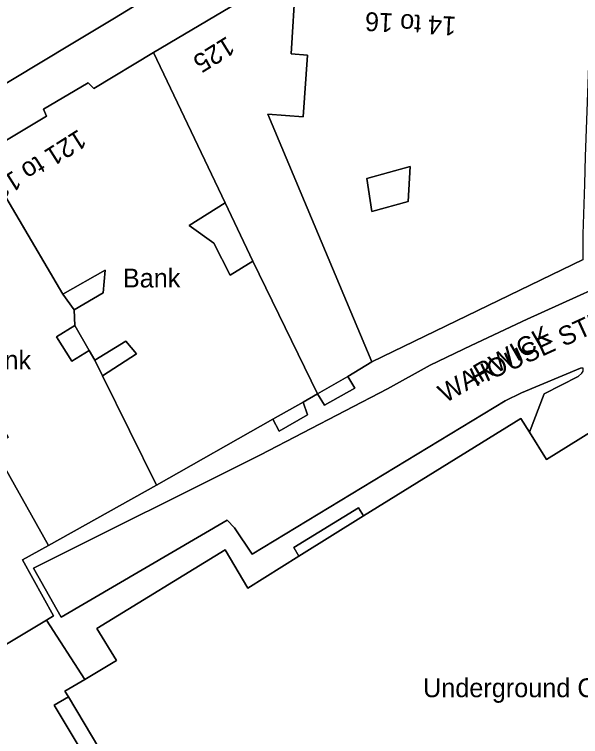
# Model space of a CAD drawing. Extents: x 529240 to 530363, y 179600 to 180767.
# Drawn here: x 529784.9 to 529829.9, y 180337.8 to 180395.2 of the extents above; entities that cross this region are included whole.
import ezdxf

# ---------------------------------------------------------------- set-up
doc = ezdxf.new("R2010")
doc.units = 0
for name, color, linetype in [('Building', 7, 'Continuous'), ('General surface', 7, 'Continuous'), ('Road Or Track', 7, 'Continuous'), ('Roadside', 7, 'Continuous'), ('Unclassified', 7, 'Continuous')]:
    doc.layers.add(name, color=color, linetype=linetype)

msp = doc.modelspace()

# ---------------------------------------------------------------- linework, layer by layer
at = {"layer": 'Building'}
for points in [[(529813.35, 180367.55), (529805.1, 180387.25), (529807.9, 180387.05), (529808.25, 180391.95), (529806.95, 180392.05), (529807.3, 180397.7), (529806.95, 180397.7), (529806.85, 180397.72), (529806.65, 180397.75), (529806.05, 180397.75), (529805.75, 180397.7), (529805.5, 180397.6), (529805.35, 180397.6), (529805.05, 180397.45), (529804.75, 180397.35), (529804.55, 180397.25), (529796, 180392.15), (529801.7, 180380.2), (529803.9, 180375.55), (529809.05, 180365), (529811.45, 180366.4)], [(529830.35, 180383.9), (529830.8, 180396.15), (529807.3, 180397.7), (529806.95, 180392.05), (529808.25, 180391.95), (529807.9, 180387.05), (529805.1, 180387.25), (529813.35, 180367.55), (529830.15, 180375.7), (529830.15, 180377.7), (529830.3, 180381.7)], [(529779.6, 180368.55), (529780.15, 180368.9), (529784.45, 180361.55), (529783.2, 180360.85), (529787.65, 180352.95), (529796.25, 180357.75), (529791.95, 180366.45), (529791.35, 180367.7), (529790.9, 180368.45), (529789.5, 180367.6), (529788.3, 180369.55), (529789.75, 180370.45), (529789.7, 180371.7), (529788.8, 180372.95), (529782.55, 180383.55), (529778.4, 180381), (529778.8, 180380.25), (529775.05, 180378.15), (529774.65, 180378.65), (529773.9, 180378.2), (529774.3, 180377.5)], [(529816.25, 180380.3), (529813.35, 180379.5), (529812.95, 180382.15), (529816.4, 180383.1)], [(529789.25, 180340.9), (529788.1, 180340.25), (529803.05, 180315.3), (529806.65, 180309.3), (529807.7, 180309.9)]]:
    msp.add_lwpolyline(points, close=True, dxfattribs=at)
for points in [[(529807.3, 180397.7), (529806.95, 180397.7), (529806.85, 180397.72), (529806.65, 180397.75), (529806.05, 180397.75), (529805.75, 180397.7), (529805.5, 180397.6), (529805.35, 180397.6), (529805.05, 180397.45), (529804.75, 180397.35), (529804.55, 180397.25), (529796, 180392.15)], [(529813.35, 180367.55), (529805.1, 180387.25), (529807.9, 180387.05), (529808.25, 180391.95), (529806.95, 180392.05), (529807.3, 180397.7)], [(529782.55, 180383.55), (529788.8, 180372.95), (529792.15, 180374.85), (529792, 180373.05), (529789.7, 180371.7), (529789.75, 180370.45), (529790.9, 180368.45), (529791.35, 180367.7), (529793.8, 180369.2), (529794.65, 180368.2), (529791.95, 180366.45), (529796.25, 180357.75), (529805.5, 180363), (529807.9, 180364.35), (529809.05, 180365), (529803.9, 180375.55), (529802.1, 180374.45), (529800.8, 180377), (529798.85, 180378.4), (529801.7, 180380.2), (529796, 180392.15), (529791.25, 180389.3), (529790.8, 180389.75), (529787.25, 180387.65), (529787.5, 180387.1), (529782.3, 180384)], [(529796, 180392.15), (529791.25, 180389.3), (529790.8, 180389.75), (529787.25, 180387.65), (529787.5, 180387.1), (529782.3, 180384), (529782.55, 180383.55)], [(529796, 180392.15), (529801.7, 180380.2)], [(529782.55, 180383.55), (529788.8, 180372.95)], [(529816.25, 180380.3), (529816.4, 180383.1), (529812.95, 180382.15), (529813.35, 180379.5), (529816.25, 180380.3)], [(529801.7, 180380.2), (529798.85, 180378.4), (529800.8, 180377), (529802.1, 180374.45), (529803.9, 180375.55)], [(529801.7, 180380.2), (529803.9, 180375.55)], [(529830.15, 180375.7), (529813.35, 180367.55)], [(529803.9, 180375.55), (529809.05, 180365)], [(529788.8, 180372.95), (529792.15, 180374.85), (529792, 180373.05), (529789.7, 180371.7)], [(529788.8, 180372.95), (529789.7, 180371.7)], [(529789.7, 180371.7), (529789.75, 180370.45)], [(529790.9, 180368.45), (529789.5, 180367.6), (529788.3, 180369.55), (529789.75, 180370.45)], [(529789.75, 180370.45), (529790.9, 180368.45)], [(529842.65, 180369.35), (529827.25, 180359.8), (529825.9, 180361.95), (529825.2, 180363.05), (529812.7, 180355.3), (529807.55, 180352.1), (529803.5, 180349.55), (529801.7, 180352.6), (529791.5, 180346.35), (529793.05, 180343.8), (529790.55, 180342.3), (529788.95, 180341.35), (529789.25, 180340.9), (529807.7, 180309.9)], [(529825.9, 180361.95), (529827.25, 180359.8), (529842.65, 180369.35)], [(529791.95, 180366.45), (529794.65, 180368.2), (529793.8, 180369.2), (529791.35, 180367.7)], [(529790.9, 180368.45), (529791.35, 180367.7)], [(529791.35, 180367.7), (529791.95, 180366.45)], [(529813.35, 180367.55), (529811.45, 180366.4)], [(529791.95, 180366.45), (529796.25, 180357.75)], [(529811.45, 180366.4), (529809.05, 180365)], [(529809.05, 180365), (529807.9, 180364.35)], [(529807.9, 180364.35), (529805.5, 180363)], [(529805.5, 180363), (529796.25, 180357.75)], [(529812.7, 180355.3), (529825.2, 180363.05), (529825.9, 180361.95)], [(529772.7, 180338.15), (529787.5, 180347), (529788.05, 180347.35), (529785.6, 180351.8), (529787.65, 180352.95), (529783.2, 180360.85)], [(529783.2, 180360.85), (529787.65, 180352.95)], [(529796.25, 180357.75), (529787.65, 180352.95)], [(529807.55, 180352.1), (529812.7, 180355.3)], [(529787.65, 180352.95), (529785.6, 180351.8), (529788.05, 180347.35), (529787.5, 180347)], [(529791.5, 180346.35), (529801.7, 180352.6), (529803.5, 180349.55), (529807.55, 180352.1)], [(529772.7, 180338.15), (529787.5, 180347)], [(529791.5, 180346.35), (529793.05, 180343.8), (529790.55, 180342.3)], [(529790.55, 180342.3), (529788.95, 180341.35), (529789.25, 180340.9)], [(529789.25, 180340.9), (529807.7, 180309.9)]]:
    msp.add_lwpolyline(points, dxfattribs=at)
at = {"layer": 'General surface'}
for points in [[(529816.25, 180380.3), (529816.4, 180383.1), (529812.95, 180382.15), (529813.35, 180379.5)], [(529803.9, 180375.55), (529801.7, 180380.2), (529798.85, 180378.4), (529800.8, 180377), (529802.1, 180374.45)], [(529789.7, 180371.7), (529792, 180373.05), (529792.15, 180374.85), (529788.8, 180372.95)], [(529790.9, 180368.45), (529789.75, 180370.45), (529788.3, 180369.55), (529789.5, 180367.6)], [(529791.35, 180367.7), (529791.95, 180366.45), (529794.65, 180368.2), (529793.8, 180369.2)], [(529809.05, 180365), (529809.6, 180364.1), (529812, 180365.45), (529811.45, 180366.4)], [(529807.9, 180364.35), (529805.5, 180363), (529806, 180362.05), (529808.25, 180363.35)], [(529812.7, 180355.3), (529812.3, 180355.95), (529807.15, 180352.8), (529807.55, 180352.1)], [(529780.5, 180336.25), (529786.65, 180326.35), (529763.65, 180314.65), (529766.65, 180303.65), (529769.75, 180297.2), (529779.85, 180309.8), (529803.05, 180315.3), (529788.1, 180340.25), (529789.25, 180340.9), (529788.95, 180341.35), (529790.55, 180342.3), (529787.5, 180347), (529772.7, 180338.15)]]:
    msp.add_lwpolyline(points, close=True, dxfattribs=at)
at = {"layer": 'Road Or Track'}
msp.add_lwpolyline([(529727.5, 180355.72), (529728.7, 180356.45), (529751.2, 180370), (529775.45, 180384.4), (529789.45, 180392.82), (529792.9, 180394.9), (529798.75, 180398.49), (529789.7, 180411.3), (529789.75, 180411), (529789.75, 180410.85), (529789.8, 180410.6), (529789.8, 180410.15), (529789.7, 180409.75), (529789.59, 180409.57), (529789.4, 180409.25), (529789, 180408.8), (529788.55, 180408.4), (529788.5, 180408.3), (529788.05, 180407.9), (529787.6, 180407.55), (529785.1, 180406.05), (529782.42, 180404.47), (529720.99, 180368.28)], close=True, dxfattribs=at)
for points in [[(529727.5, 180355.72), (529728.7, 180356.45), (529751.2, 180370), (529775.45, 180384.4), (529789.45, 180392.82), (529792.9, 180394.9), (529798.75, 180398.49)], [(529825.9, 180361.95), (529827.05, 180365), (529829.75, 180366.4), (529830.05, 180366.65), (529830.15, 180366.8), (529830.15, 180367.05), (529829.95, 180367.05), (529825.25, 180365.1), (529823.95, 180364.45), (529803.85, 180352.25), (529802.45, 180354.35), (529801.85, 180354.95), (529788.65, 180347.25), (529786.45, 180351.15), (529804.5, 180360.15), (529814.6, 180365.4), (529818, 180367.3), (529821.25, 180368.85), (529825.7, 180370.95), (529834.95, 180375.15), (529839.15, 180377.2), (529840.45, 180377.95), (529855.17, 180383.52)], [(529834.95, 180375.15), (529825.7, 180370.95), (529821.25, 180368.85), (529818, 180367.3), (529814.6, 180365.4), (529804.5, 180360.15), (529786.45, 180351.15), (529788.65, 180347.25), (529801.85, 180354.95), (529802.45, 180354.35), (529803.85, 180352.25), (529823.95, 180364.45), (529825.25, 180365.1), (529829.95, 180367.05)], [(529830.05, 180366.65), (529829.75, 180366.4), (529827.05, 180365), (529825.9, 180361.95), (529827.25, 180359.8), (529842.65, 180369.35)]]:
    msp.add_lwpolyline(points, dxfattribs=at)
at = {"layer": 'Roadside'}
for points in [[(529798.75, 180398.49), (529792.9, 180394.9), (529789.45, 180392.82), (529775.45, 180384.4)], [(529782.3, 180384), (529787.5, 180387.1), (529787.25, 180387.65), (529790.8, 180389.75), (529791.25, 180389.3), (529796, 180392.15), (529804.55, 180397.25)], [(529830.15, 180375.7), (529813.35, 180367.55), (529811.45, 180366.4), (529812, 180365.45), (529809.6, 180364.1), (529809.05, 180365), (529807.9, 180364.35), (529808.25, 180363.35), (529806, 180362.05), (529805.5, 180363), (529796.25, 180357.75), (529787.65, 180352.95), (529785.6, 180351.8), (529788.05, 180347.35), (529787.5, 180347), (529790.55, 180342.3), (529793.05, 180343.8), (529791.5, 180346.35), (529801.7, 180352.6), (529803.5, 180349.55), (529807.55, 180352.1), (529807.15, 180352.8), (529812.3, 180355.95), (529812.7, 180355.3), (529825.2, 180363.05), (529825.9, 180361.95), (529827.05, 180365), (529829.75, 180366.4), (529830.05, 180366.65)], [(529829.95, 180367.05), (529825.25, 180365.1), (529823.95, 180364.45), (529803.85, 180352.25), (529802.45, 180354.35), (529801.85, 180354.95), (529788.65, 180347.25), (529786.45, 180351.15), (529804.5, 180360.15), (529814.6, 180365.4), (529818, 180367.3), (529821.25, 180368.85), (529825.7, 180370.95), (529834.95, 180375.15)]]:
    msp.add_lwpolyline(points, dxfattribs=at)
at = {"layer": 'Unclassified'}
for points in [[(529811.45, 180366.4), (529812, 180365.45), (529809.6, 180364.1), (529809.05, 180365)], [(529807.9, 180364.35), (529808.25, 180363.35), (529806, 180362.05), (529805.5, 180363)], [(529807.55, 180352.1), (529807.15, 180352.8), (529812.3, 180355.95), (529812.7, 180355.3)], [(529787.5, 180347), (529790.55, 180342.3)], [(529789.25, 180340.9), (529788.1, 180340.25), (529803.05, 180315.3)]]:
    msp.add_lwpolyline(points, dxfattribs=at)

# ---------------------------------------------------------------- texts
at = {"layer": 'Road Or Track'}
for s, rotation, p in [('HOUSE STREET', 24.5, (529821.6, 180365.55)), ('WARWICK', 30, (529819.2, 180364.25))]:
    msp.add_text(s, height=1.5, rotation=rotation, dxfattribs=at).set_placement(p)
at = {"layer": 'Unclassified'}
for s, rotation, p in [('14 to 16', 177, (529820.1, 180395)), ('125', 211.8, (529801.85, 180393.5)), ('121 to 123', 212.3, (529790.05, 180386.1))]:
    msp.add_text(s, height=1.5, rotation=rotation, dxfattribs=at).set_placement(p)
for s, p in [('Bank', (529793.57, 180373.47)), ('Bank', (529781.7, 180366.95)), ('Underground Car ', (529817.43, 180340.88))]:
    msp.add_text(s, height=1.5, dxfattribs=at).set_placement(p)

doc.saveas('drawing.dxf')
